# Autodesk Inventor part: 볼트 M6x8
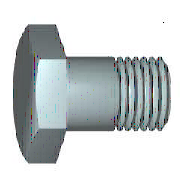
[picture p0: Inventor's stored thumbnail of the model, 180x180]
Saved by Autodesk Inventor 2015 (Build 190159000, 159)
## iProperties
Created: 2012-02
Part Number: 볼트 M6x8
Material: 강철, 연강
Description: 6각 머리 볼트 및 6각 머리 나사
Document SubType Name: Modeling
Standard: KS B 1002
Designer: mduedu
Standards Organization: KS
Language: ko-KR
Size Designation: C  M 6 x 12
Categories: <MemberInstance><Categories><Category DisplayName="조임쇠" InternalName="e4da775c-781d-43d5-af7c-5136215cf5a6" Mnemonic="FSTN"><Category DisplayName="볼트" InternalN
Density: 1 g/cm^3
Appearance: 강철
IsCustomPart: 1
Author: mduedu
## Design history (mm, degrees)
sketch "스케치1"
  geometry: L1 (0, 3)-(8, 3); L2 (8, 3)-(8, 0); L3 (8, 0)-(0, 0); L4 (-2.4, 0)-(14.4, 0) reference; L5 (0, -0.6)-(0, 3.6) reference; L6 (0, 3)-(0, 0)
  constraints: 8 end point, 3 point on line, 1 collinear
  dimensions: "d2" = 6 diameter of L1 L3 (= GD); "d59" = 8 distance between parallel lines of L2 L5 (= NLG)
revolve "본체" sketch "스케치1" stored, may be unused: angle "d12" = 90 deg
sketch "스케치2"
  geometry: L1 (0, 5.774)-(5, 2.887); L2 (5, 2.887)-(5, -2.887); L3 (5, -2.887)-(0, -5.774); L4 (0, -5.774)-(-5, -2.887); L5 (-5, -2.887)-(-5, 2.887); L6 (-5, 2.887)-(0, 5.774); L7 (-7, 0)-(7, 0) reference; L8 (0, 8.083)-(0, -8.083) reference; 2 further points
  constraints: 12 end point, 2 midpoint, 1 coincident, 1 vertical, 11 other
  dimensions: "d11" = 10 distance between parallel lines of L5 L2 (= SW)
extrude "머리" join sketch "스케치2" distance "d3" = 4 (= KOH); taper "d4" = 0 deg
revolve "모따기1" stored, may be unused: angle "d21" = 90 deg
workplane "Work Plane1"
body "Solid1"
feature "스레드" dims "d15" = 9 (= GEL), "d16" = 0
chamfer "모따기2" distance "d6" = 0.61345 (= -0.5 x SPD + 0.5 x GD); stored, may be unused: second distance "d7" = 0.61355 (computed from GUL), angle "d55" = 45 deg
sketch "스케치4"
  geometry: L1 (-3.423, 6)-(-4, 5); L2 (-1.1, 0)-(-0.234, 0); L3 (-4.753, 0)-(0.519, 0) reference; L4 (-4, 6)-(-3.423, 6); L5 (-4, 5)-(-4, 6); L6 (0, 7.2)-(0, -1.2) reference
  constraints: 8 end point, 1 parallel, 1 perpendicular, 1 point on line
  dimensions: "d65" = 10 diameter of L1.end L2 (= SW); "d67" = 30 deg angle of L1 L5 (= ANG1); "d68" = 12 diameter of L4 L2 (= 1.2 x SW); "d69" = 4 distance between parallel lines of L5 L6 (= KOH)
other parameters: "NLG" = 8 [user parameter; used in 1 equation term], "GD" = 6 (= NND) [user parameter; used in 2 equation terms], "BDM" = 6 (= NND) [user parameter], "KOH" = 4 [user parameter; used in 2 equation terms], "GEL" = 9 [user parameter; used in 1 equation term], "SW" = 10 [user parameter; used in 5 equation terms], "SPD" = 4.7731 (= NND - 1.2269 x PTC) [user parameter; used in 1 equation term], "SD2" = 6 (= NND) [user parameter], "SD" = 0 [user parameter], "ANG1" = 30 deg [user parameter; used in 1 equation term], "GAL" = 0.61345 (= 0.61345 x PTC) [user parameter], "GUL" = 0.61345 (= 0.61345 x PTC) [user parameter; used in 1 equation term], "d8" = 0, "RR" = 0.25 [user parameter], "d58" = 0, "RR1" = 0.1 [user parameter], "GD1" = 4.7731 (= THREADDIA - 1.2269 x PTC) [user parameter], "THREADDIA" = 6 [user parameter; used in 1 equation term], "TOA" = 30 deg [user parameter], "PTC" = 1 [user parameter; used in 5 equation terms], "NND" = 6 [user parameter; used in 4 equation terms], "E0" = 11.55 (= 1.155 x SW) [user parameter]
